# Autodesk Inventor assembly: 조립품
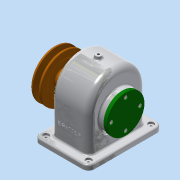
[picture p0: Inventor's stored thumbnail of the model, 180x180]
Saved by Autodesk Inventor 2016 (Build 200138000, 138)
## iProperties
Created: 2018-11
Part Number: 조립품
Material: 일반
Document SubType Name: Assembly
Designer: user
Author: user
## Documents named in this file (14)
- C:\Users\user\Desktop\481111V1004\조립품.iam
- C:\Users\user\Desktop\481111V1004\V-벨트풀리.ipt
- C:\Users\user\Desktop\481111V1004\뒤커버.ipt
- C:\Users\user\Desktop\481111V1004\멈춤나사 M4.ipt
- C:\Users\user\Desktop\481111V1004\베어링 6203.ipt
- C:\Users\user\Desktop\481111V1004\본체.ipt
- C:\Users\user\Desktop\481111V1004\볼트 M4.ipt
- C:\Users\user\Desktop\481111V1004\부시.ipt
- C:\Users\user\Desktop\481111V1004\스퍼기어.ipt
- C:\Users\user\Desktop\481111V1004\앞커버.ipt
- C:\Users\user\Desktop\481111V1004\오일 실 28 40 8.ipt
- C:\Users\user\Desktop\481111V1004\축.ipt
- C:\Users\user\Desktop\481111V1004\키 5x5x18.ipt
- C:\Users\user\Desktop\481111V1004\키 6x6x22.ipt
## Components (1 placed, 1 different names)
1. V-벨트풀리:1
